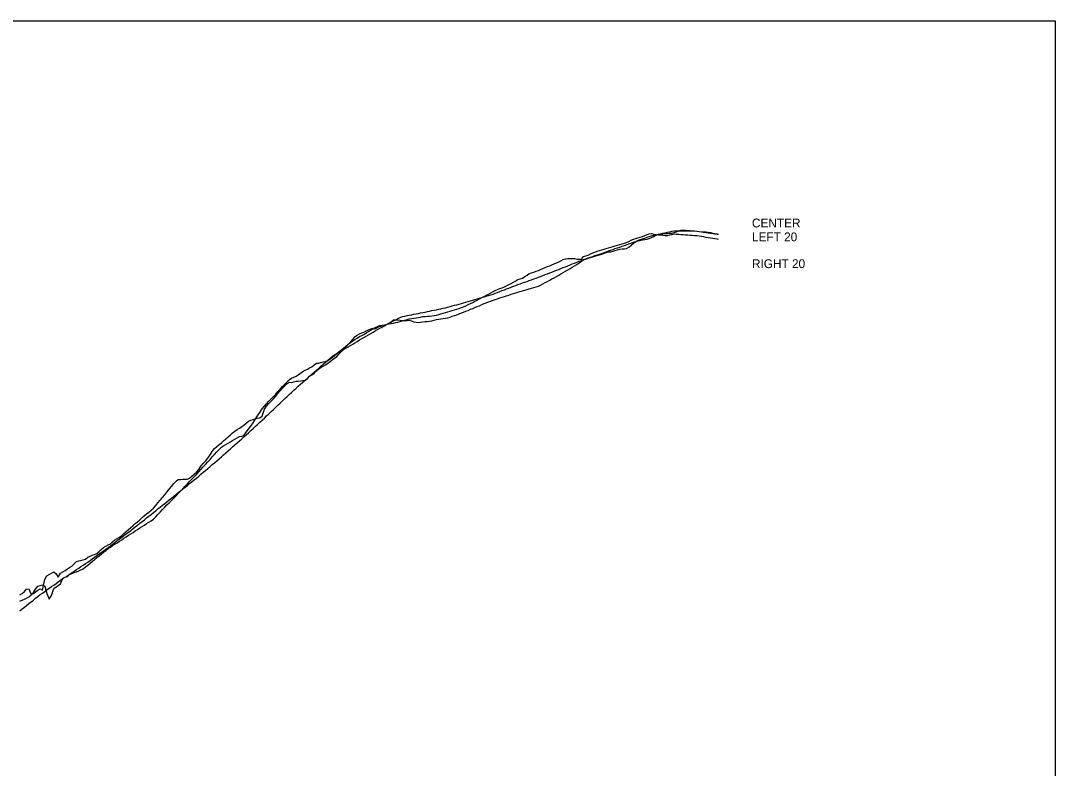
# Model space of a CAD drawing. Extents: x 1511486 to 1516886, y 901686 to 906985.
# Drawn here: x 1514602 to 1516886, y 905335 to 906985 of the extents above; entities that cross this region are included whole.
import ezdxf

# ---------------------------------------------------------------- set-up
doc = ezdxf.new("R2010")
doc.units = 0
for name, color, linetype in [('RD_DDB_Profile_EX', 7, 'Continuous'), ('RD_Sketch2', 7, 'Continuous'), ('RD_Sketch3', 7, 'Continuous')]:
    doc.layers.add(name, color=color, linetype=linetype)

msp = doc.modelspace()

# ---------------------------------------------------------------- linework, layer by layer
at = {"layer": 'RD_DDB_Profile_EX'}
for points in [[(1515574.7, 906361.2), (1515579.7, 906362.6), (1515584.7, 906364), (1515589.7, 906365.3), (1515594.7, 906366.8), (1515599.7, 906368.3), (1515604.7, 906369.8), (1515609.7, 906371.3), (1515614.7, 906372.8), (1515619.7, 906374.3), (1515624.7, 906375.7), (1515629.7, 906377.2), (1515634.7, 906378.7), (1515639.7, 906380.2), (1515644.7, 906381.9), (1515649.7, 906383.8), (1515654.7, 906385.7), (1515659.7, 906387.6), (1515664.7, 906389.5), (1515669.7, 906391.4), (1515674.7, 906393.4), (1515679.7, 906395.3), (1515684.7, 906397.2), (1515689.7, 906399.1), (1515694.7, 906401), (1515699.7, 906402.8), (1515704.7, 906404.6), (1515709.7, 906406.4), (1515714.7, 906408.2), (1515719.7, 906410), (1515724.7, 906411.8), (1515729.7, 906413.6), (1515734.7, 906415.4), (1515739.7, 906417.2), (1515744.7, 906419), (1515749.7, 906421), (1515754.7, 906422.9), (1515759.7, 906424.8), (1515764.7, 906426.7), (1515769.7, 906428.7), (1515774.7, 906430.6), (1515779.7, 906432.5), (1515784.7, 906434.4), (1515789.7, 906436.3), (1515794.7, 906438.3), (1515799.7, 906440.3), (1515804.7, 906442.3), (1515809.7, 906444.3), (1515814.7, 906446.3), (1515819.7, 906448.3), (1515824.7, 906450.3), (1515829.7, 906452.3), (1515834.7, 906454.3), (1515839.7, 906456.3), (1515844.7, 906458.2), (1515849.7, 906459.9), (1515854.7, 906461.6), (1515859.7, 906463.3), (1515864.7, 906465), (1515869.7, 906466.7), (1515874.7, 906468.4), (1515879.7, 906470.1), (1515884.7, 906471.8), (1515889.7, 906473.5), (1515894.7, 906475.2), (1515899.7, 906477), (1515904.7, 906478.7), (1515909.7, 906480.5), (1515914.7, 906482.2), (1515919.7, 906483.9), (1515924.7, 906485.7), (1515929.7, 906487.4), (1515934.7, 906489.1), (1515939.7, 906490.9), (1515944.7, 906492.8), (1515949.7, 906494.6), (1515954.7, 906496.4), (1515959.7, 906498.2), (1515964.7, 906500.2), (1515969.7, 906502), (1515974.7, 906503.8), (1515979.7, 906505.6), (1515984.7, 906507.4), (1515989.7, 906509.2), (1515994.7, 906510.5), (1515999.7, 906511.7), (1516004.7, 906512.8), (1516009.7, 906513.9), (1516014.7, 906515.1), (1516019.7, 906516.2), (1516024.7, 906517.3), (1516029.7, 906518.5), (1516034.7, 906519.6), (1516039.7, 906520.8), (1516044.7, 906521.3), (1516049.7, 906521.4), (1516054.7, 906521.4), (1516059.7, 906521.5), (1516064.7, 906521.6), (1516069.7, 906521.7), (1516074.7, 906521.7)], [(1516074.7, 906521.7), (1516079.7, 906521.6), (1516084.7, 906521.6), (1516089.7, 906521.5), (1516094.7, 906521), (1516099.7, 906520.2), (1516104.7, 906519.5), (1516109.7, 906518.7), (1516114.7, 906517.9), (1516119.7, 906517.1), (1516124.7, 906516.3), (1516129.7, 906515.5), (1516134.7, 906514.7), (1516139.7, 906513.9), (1516141.8, 906513.6)], [(1515074.7, 906049), (1515079.7, 906053.5), (1515084.7, 906057.9), (1515089.7, 906062.4), (1515094.7, 906066.8), (1515099.7, 906071.4), (1515104.7, 906076), (1515109.7, 906080.6), (1515114.7, 906085.2), (1515119.7, 906089.8), (1515124.7, 906094.4), (1515129.7, 906099.1), (1515134.7, 906103.7), (1515139.7, 906108.3), (1515144.7, 906112.9), (1515149.7, 906117.7), (1515154.7, 906122.4), (1515159.7, 906127.2), (1515164.7, 906132), (1515169.7, 906136.8), (1515174.7, 906141.5), (1515179.7, 906146.3), (1515184.7, 906151.1), (1515189.7, 906155.9), (1515194.7, 906160.5), (1515199.7, 906165), (1515204.7, 906169.5), (1515209.7, 906174), (1515214.7, 906178.5), (1515219.7, 906183), (1515224.7, 906187.5), (1515229.7, 906192), (1515234.7, 906196.5), (1515239.7, 906201), (1515244.7, 906205.4), (1515249.7, 906209.8), (1515254.7, 906214.2), (1515259.7, 906218.6), (1515264.7, 906222.9), (1515269.7, 906227.3), (1515274.7, 906231.6), (1515279.7, 906235.8), (1515284.7, 906240.1), (1515289.7, 906244.3), (1515294.7, 906248.1), (1515299.7, 906251.1), (1515304.7, 906253.9), (1515309.7, 906256.9), (1515314.7, 906259.9), (1515319.7, 906262.8), (1515324.7, 906265.7), (1515329.7, 906268.6), (1515334.7, 906271.5), (1515339.7, 906274.5), (1515344.7, 906277.6), (1515349.7, 906280.6), (1515354.7, 906283.5), (1515359.7, 906286.4), (1515364.7, 906289.3), (1515369.7, 906292.1), (1515374.7, 906295.1), (1515379.7, 906298.1), (1515384.7, 906300.9), (1515389.7, 906303.7), (1515394.7, 906306.5), (1515399.7, 906309.2), (1515404.7, 906312), (1515409.7, 906314.7), (1515414.7, 906317.1), (1515419.7, 906319.8), (1515424.7, 906322.5), (1515429.7, 906325.2), (1515434.7, 906327.9), (1515439.7, 906330.5), (1515444.7, 906332.3), (1515449.7, 906333.3), (1515454.7, 906334.3), (1515459.7, 906335.3), (1515464.7, 906336.3), (1515469.7, 906337.3), (1515474.7, 906338.3), (1515479.7, 906339.3), (1515484.7, 906340.3), (1515489.7, 906341.3), (1515494.7, 906342.2), (1515499.7, 906343.3), (1515504.7, 906344.5), (1515509.7, 906345.5), (1515514.7, 906346.2), (1515519.7, 906347.3), (1515524.7, 906348.5), (1515529.7, 906349.6), (1515534.7, 906350.7), (1515539.7, 906351.9), (1515544.7, 906353.1), (1515549.7, 906354.4), (1515554.7, 906355.8), (1515559.7, 906357.1), (1515564.7, 906358.4), (1515569.7, 906359.8), (1515574.7, 906361.2)], [(1514599.7, 905682.9), (1514604.7, 905686.9), (1514609.7, 905690.8), (1514614.7, 905694.8), (1514619.7, 905698.7), (1514624.7, 905702.7), (1514629.7, 905706.6), (1514634.7, 905710.5), (1514639.7, 905714.5), (1514644.7, 905718.5), (1514649.7, 905722), (1514654.7, 905725.5), (1514659.7, 905729.1), (1514664.7, 905732.6), (1514669.7, 905736.2), (1514674.7, 905739.7), (1514679.7, 905743.2), (1514684.7, 905746.8), (1514689.7, 905750.3), (1514694.7, 905753.8), (1514699.7, 905757.1), (1514704.7, 905760.4), (1514709.7, 905763.8), (1514714.7, 905767), (1514719.7, 905770.4), (1514724.7, 905773.7), (1514729.7, 905777), (1514734.7, 905780.3), (1514739.7, 905783.6), (1514744.7, 905786.9), (1514749.7, 905790.5), (1514754.7, 905794), (1514759.7, 905797.6), (1514764.7, 905801.1), (1514769.7, 905804.7), (1514774.7, 905808.3), (1514779.7, 905811.8), (1514784.7, 905815.4), (1514789.7, 905819), (1514794.7, 905822.6), (1514799.7, 905826.3), (1514804.7, 905830.1), (1514809.7, 905833.9), (1514814.7, 905837.7), (1514819.7, 905841.4), (1514824.7, 905845.2), (1514829.7, 905849), (1514834.7, 905852.8), (1514839.7, 905856.5), (1514844.7, 905860.3), (1514849.7, 905864.2), (1514854.7, 905868.2), (1514859.7, 905872.1), (1514864.7, 905876), (1514869.7, 905880), (1514874.7, 905883.9), (1514879.7, 905887.8), (1514884.7, 905891.7), (1514889.7, 905895.6), (1514894.7, 905899.5), (1514899.7, 905903.5), (1514904.7, 905907.6), (1514909.7, 905911.6), (1514914.7, 905915.7), (1514919.7, 905919.6), (1514924.7, 905923.6), (1514929.7, 905927.6), (1514934.7, 905931.6), (1514939.7, 905935.6), (1514944.7, 905939.6), (1514949.7, 905943.6), (1514954.7, 905947.6), (1514959.7, 905951.7), (1514964.7, 905955.7), (1514969.7, 905959.7), (1514974.7, 905963.7), (1514979.7, 905967.8), (1514984.7, 905971.8), (1514989.7, 905975.9), (1514994.7, 905980), (1514999.7, 905984.2), (1515004.7, 905988.5), (1515009.7, 905992.7), (1515014.7, 905996.9), (1515019.7, 906001.2), (1515024.7, 906005.4), (1515029.7, 906009.6), (1515034.7, 906013.9), (1515039.7, 906018.2), (1515044.7, 906022.6), (1515049.7, 906027), (1515054.7, 906031.4), (1515059.7, 906035.8), (1515064.7, 906040.2), (1515069.7, 906044.6), (1515074.7, 906049)]]:
    msp.add_lwpolyline(points, dxfattribs=at)
at = {"layer": 'RD_Sketch2'}
for points in [[(1515574.7, 906340.2), (1515579.7, 906342.1), (1515584.7, 906344), (1515589.7, 906345.9), (1515594.7, 906348.4), (1515599.7, 906350.3), (1515604.7, 906352.3), (1515609.7, 906354.2), (1515614.7, 906356.1), (1515619.7, 906358.7), (1515624.7, 906360.8), (1515629.7, 906362.7), (1515634.7, 906364.5), (1515639.7, 906366.4), (1515644.7, 906368.3), (1515649.7, 906369.7), (1515654.7, 906371.5), (1515659.7, 906373.4), (1515664.7, 906374.8), (1515669.7, 906376.4), (1515674.7, 906378.1), (1515679.7, 906379.7), (1515684.7, 906381.4), (1515689.7, 906383.2), (1515694.7, 906384.8), (1515699.7, 906386.3), (1515704.7, 906387.7), (1515709.7, 906389.3), (1515714.7, 906390.7), (1515719.7, 906392.1), (1515724.7, 906393.4), (1515729.7, 906394.8), (1515734.7, 906396.2), (1515739.7, 906397.6), (1515744.7, 906399.6), (1515749.7, 906401.8), (1515754.7, 906404.7), (1515759.7, 906407.3), (1515764.7, 906410), (1515769.7, 906412.7), (1515774.7, 906415.4), (1515779.7, 906418.1), (1515784.7, 906420.8), (1515789.7, 906423.6), (1515794.7, 906426.4), (1515799.7, 906429.4), (1515804.7, 906432.3), (1515809.7, 906435.3), (1515814.7, 906438.2), (1515819.7, 906441.2), (1515824.7, 906444), (1515829.7, 906447.1), (1515834.7, 906450.7), (1515839.7, 906454.7), (1515844.7, 906457.5), (1515849.7, 906459.2), (1515854.7, 906460.9), (1515859.7, 906462.5), (1515864.7, 906463.9), (1515869.7, 906465.4), (1515874.7, 906466.9), (1515879.7, 906468.5), (1515884.7, 906470.2), (1515889.7, 906471.9), (1515894.7, 906473.7), (1515899.7, 906475), (1515904.7, 906475.5), (1515909.7, 906476.8), (1515914.7, 906478.1), (1515919.7, 906479.5), (1515924.7, 906480.9), (1515929.7, 906481.7), (1515934.7, 906482), (1515939.7, 906482.3), (1515944.7, 906485.5), (1515949.7, 906489.8), (1515954.7, 906494.2), (1515959.7, 906498.2), (1515964.7, 906499.3), (1515969.7, 906500.3), (1515974.7, 906501.3), (1515979.7, 906502.4), (1515984.7, 906503.4), (1515989.7, 906504.5), (1515994.7, 906506.6), (1515999.7, 906509.2), (1516004.7, 906511.7), (1516009.7, 906514.3), (1516014.7, 906514.8), (1516019.7, 906515.1), (1516024.7, 906515.4), (1516029.7, 906515.7), (1516034.7, 906516.1), (1516039.7, 906516.4), (1516044.7, 906517.6), (1516049.7, 906519.5), (1516054.7, 906521.4), (1516059.7, 906523.3), (1516064.7, 906523), (1516069.7, 906522.7), (1516074.7, 906522.4)], [(1516074.7, 906522.4), (1516079.7, 906522.1), (1516084.7, 906521.8), (1516089.7, 906521.5), (1516094.7, 906520.5), (1516099.7, 906519.8), (1516104.7, 906519.5), (1516109.7, 906519.3), (1516114.7, 906519), (1516119.7, 906518.6), (1516124.7, 906517.6), (1516129.7, 906516.7), (1516134.7, 906515.8), (1516139.7, 906514.8), (1516141.8, 906514.4)], [(1515574.7, 906352.1), (1515579.7, 906354), (1515584.7, 906356.3), (1515589.7, 906358.6), (1515594.7, 906360.8), (1515599.7, 906363.5), (1515604.7, 906366.1), (1515609.7, 906368.8), (1515614.7, 906371.4), (1515619.7, 906374), (1515624.7, 906376.7), (1515629.7, 906379.3), (1515634.7, 906382), (1515639.7, 906384.6), (1515644.7, 906387.3), (1515649.7, 906390), (1515654.7, 906392.1), (1515659.7, 906394), (1515664.7, 906395.9), (1515669.7, 906397.8), (1515674.7, 906400.1), (1515679.7, 906402.7), (1515684.7, 906405.3), (1515689.7, 906407.9), (1515694.7, 906410.8), (1515699.7, 906413.8), (1515704.7, 906415.4), (1515709.7, 906417.3), (1515714.7, 906420.6), (1515719.7, 906423.9), (1515724.7, 906427.2), (1515729.7, 906429), (1515734.7, 906430.5), (1515739.7, 906432.1), (1515744.7, 906433.9), (1515749.7, 906436), (1515754.7, 906438.1), (1515759.7, 906440.3), (1515764.7, 906442.4), (1515769.7, 906444.4), (1515774.7, 906446.5), (1515779.7, 906448.5), (1515784.7, 906450.6), (1515789.7, 906452.7), (1515794.7, 906455.2), (1515799.7, 906458.2), (1515804.7, 906459.9), (1515809.7, 906460.4), (1515814.7, 906460.3), (1515819.7, 906460.2), (1515824.7, 906460.1), (1515829.7, 906459), (1515834.7, 906458.9), (1515839.7, 906458.9), (1515844.7, 906465.2), (1515849.7, 906466), (1515854.7, 906468), (1515859.7, 906470.7), (1515864.7, 906472.7), (1515869.7, 906474.5), (1515874.7, 906476.3), (1515879.7, 906478), (1515884.7, 906479.7), (1515889.7, 906480.9), (1515894.7, 906482.4), (1515899.7, 906483.8), (1515904.7, 906485.3), (1515909.7, 906486.9), (1515914.7, 906488.4), (1515919.7, 906489.9), (1515924.7, 906491.4), (1515929.7, 906492.9), (1515934.7, 906494.4), (1515939.7, 906496), (1515944.7, 906498.3), (1515949.7, 906500.6), (1515954.7, 906502.8), (1515959.7, 906504.6), (1515964.7, 906506.4), (1515969.7, 906507.6), (1515974.7, 906508.8), (1515979.7, 906511.5), (1515984.7, 906513.7), (1515989.7, 906515.2), (1515994.7, 906515.7), (1515999.7, 906514.3), (1516004.7, 906513.3), (1516009.7, 906512.8), (1516014.7, 906512.3), (1516019.7, 906511.8), (1516024.7, 906511.4), (1516029.7, 906511.4), (1516034.7, 906512.5), (1516039.7, 906513.6), (1516044.7, 906514.6), (1516049.7, 906514.4), (1516054.7, 906514.1), (1516059.7, 906513.7), (1516064.7, 906513.2), (1516069.7, 906512.8), (1516074.7, 906512.5)], [(1516074.7, 906512.5), (1516079.7, 906512.2), (1516084.7, 906511.8), (1516089.7, 906511.5), (1516094.7, 906511), (1516099.7, 906510.4), (1516104.7, 906509.6), (1516109.7, 906508.7), (1516114.7, 906507.8), (1516119.7, 906506.9), (1516124.7, 906506.1), (1516129.7, 906505.2), (1516134.7, 906504.4), (1516139.7, 906503.7), (1516141.8, 906503.4)], [(1515074.7, 906079.7), (1515079.7, 906083.1), (1515084.7, 906086.3), (1515089.7, 906089.4), (1515094.7, 906092.7), (1515099.7, 906097.2), (1515104.7, 906101.1), (1515109.7, 906103.3), (1515114.7, 906104.9), (1515119.7, 906106.3), (1515124.7, 906107.7), (1515129.7, 906108.8), (1515134.7, 906112.1), (1515139.7, 906128.1), (1515144.7, 906134.2), (1515149.7, 906140.1), (1515154.7, 906145.6), (1515159.7, 906151), (1515164.7, 906156.7), (1515169.7, 906162.5), (1515174.7, 906168.3), (1515179.7, 906174.1), (1515184.7, 906179.7), (1515189.7, 906184.5), (1515194.7, 906187.7), (1515199.7, 906187), (1515204.7, 906188.2), (1515209.7, 906189.4), (1515214.7, 906190), (1515219.7, 906190.6), (1515224.7, 906191.2), (1515229.7, 906191.8), (1515234.7, 906195.8), (1515239.7, 906200.5), (1515244.7, 906203.9), (1515249.7, 906207.2), (1515254.7, 906212.2), (1515259.7, 906216.9), (1515264.7, 906219.7), (1515269.7, 906222.5), (1515274.7, 906225.7), (1515279.7, 906229.3), (1515284.7, 906233.1), (1515289.7, 906237.1), (1515294.7, 906240.8), (1515299.7, 906244.4), (1515304.7, 906250.1), (1515309.7, 906255.3), (1515314.7, 906260.2), (1515319.7, 906265.3), (1515324.7, 906270.6), (1515329.7, 906276), (1515334.7, 906281.6), (1515339.7, 906287.5), (1515344.7, 906291), (1515349.7, 906294.2), (1515354.7, 906296.2), (1515359.7, 906298.2), (1515364.7, 906300.5), (1515369.7, 906302.9), (1515374.7, 906305.2), (1515379.7, 906307), (1515384.7, 906305.3), (1515389.7, 906308.3), (1515394.7, 906311.1), (1515399.7, 906309.7), (1515404.7, 906312), (1515409.7, 906314.9), (1515414.7, 906316.1), (1515419.7, 906317.2), (1515424.7, 906318), (1515429.7, 906319), (1515434.7, 906320.2), (1515439.7, 906321.6), (1515444.7, 906322.6), (1515449.7, 906324.2), (1515454.7, 906326), (1515459.7, 906327.3), (1515464.7, 906328), (1515469.7, 906328.9), (1515474.7, 906329.8), (1515479.7, 906330.3), (1515484.7, 906331.1), (1515489.7, 906332.1), (1515494.7, 906332.5), (1515499.7, 906332.8), (1515504.7, 906333.1), (1515509.7, 906333.7), (1515514.7, 906334.6), (1515519.7, 906335.7), (1515524.7, 906336.8), (1515529.7, 906338.1), (1515534.7, 906339.6), (1515539.7, 906341.3), (1515544.7, 906342.9), (1515549.7, 906344.2), (1515554.7, 906345.4), (1515559.7, 906346.8), (1515564.7, 906348.4), (1515569.7, 906350.2), (1515574.7, 906352.1)], [(1515074.7, 906061.5), (1515079.7, 906064.4), (1515084.7, 906067.3), (1515089.7, 906068.6), (1515094.7, 906069.9), (1515099.7, 906077.3), (1515104.7, 906083.4), (1515109.7, 906090.2), (1515114.7, 906097.7), (1515119.7, 906105.3), (1515124.7, 906112.9), (1515129.7, 906120.7), (1515134.7, 906128.5), (1515139.7, 906134.8), (1515144.7, 906139.9), (1515149.7, 906145.4), (1515154.7, 906150.9), (1515159.7, 906156.1), (1515164.7, 906161.3), (1515169.7, 906166.7), (1515174.7, 906172.1), (1515179.7, 906177.6), (1515184.7, 906183.1), (1515189.7, 906188.5), (1515194.7, 906192.7), (1515199.7, 906196), (1515204.7, 906198.3), (1515209.7, 906200.5), (1515214.7, 906203.4), (1515219.7, 906207.1), (1515224.7, 906210.7), (1515229.7, 906214), (1515234.7, 906216.4), (1515239.7, 906218.8), (1515244.7, 906221.3), (1515249.7, 906226), (1515254.7, 906229.2), (1515259.7, 906229.2), (1515264.7, 906230.8), (1515269.7, 906232.2), (1515274.7, 906233.3), (1515279.7, 906235.3), (1515284.7, 906238.7), (1515289.7, 906242.1), (1515294.7, 906246.7), (1515299.7, 906250.9), (1515304.7, 906254.9), (1515309.7, 906258.8), (1515314.7, 906262.8), (1515319.7, 906267), (1515324.7, 906271), (1515329.7, 906274.9), (1515334.7, 906278.7), (1515339.7, 906281.7), (1515344.7, 906284.4), (1515349.7, 906288.2), (1515354.7, 906290.5), (1515359.7, 906292.7), (1515364.7, 906296), (1515369.7, 906299.3), (1515374.7, 906302.5), (1515379.7, 906305.5), (1515384.7, 906308.1), (1515389.7, 906310.5), (1515394.7, 906312.2), (1515399.7, 906313.2), (1515404.7, 906314.1), (1515409.7, 906315), (1515414.7, 906317.7), (1515419.7, 906320.3), (1515424.7, 906325), (1515429.7, 906325.2), (1515434.7, 906324.9), (1515439.7, 906324.6), (1515444.7, 906323.5), (1515449.7, 906323.2), (1515454.7, 906323.8), (1515459.7, 906324.3), (1515464.7, 906323), (1515469.7, 906321), (1515474.7, 906319.6), (1515479.7, 906319.2), (1515484.7, 906319.9), (1515489.7, 906320.7), (1515494.7, 906321.4), (1515499.7, 906321.6), (1515504.7, 906321.9), (1515509.7, 906322.7), (1515514.7, 906324.3), (1515519.7, 906325.9), (1515524.7, 906326.5), (1515529.7, 906327.1), (1515534.7, 906327.7), (1515539.7, 906328.4), (1515544.7, 906329.2), (1515549.7, 906331), (1515554.7, 906332.8), (1515559.7, 906334.7), (1515564.7, 906336.4), (1515569.7, 906338.4), (1515574.7, 906340.2)], [(1514599.7, 905717.8), (1514604.7, 905720.8), (1514609.7, 905725.7), (1514614.7, 905730.7), (1514619.7, 905731.1), (1514624.7, 905718.6), (1514629.7, 905720.9), (1514634.7, 905724.6), (1514639.7, 905728.2), (1514644.7, 905731), (1514649.7, 905728.2), (1514654.7, 905751.8), (1514659.7, 905760), (1514664.7, 905762.9), (1514669.7, 905765.8), (1514674.7, 905768.7), (1514679.7, 905764.8), (1514684.7, 905757.3), (1514689.7, 905765.8), (1514694.7, 905769), (1514699.7, 905772.1), (1514704.7, 905775.3), (1514709.7, 905778.1), (1514714.7, 905781.7), (1514719.7, 905786.7), (1514724.7, 905791.8), (1514729.7, 905793.1), (1514734.7, 905794.2), (1514739.7, 905795.3), (1514744.7, 905796.8), (1514749.7, 905801.5), (1514754.7, 905803.5), (1514759.7, 905805.5), (1514764.7, 905807.4), (1514769.7, 905809.3), (1514774.7, 905813.8), (1514779.7, 905818.2), (1514784.7, 905822.6), (1514789.7, 905825.7), (1514794.7, 905828.3), (1514799.7, 905830.9), (1514804.7, 905834.8), (1514809.7, 905839.4), (1514814.7, 905842.4), (1514819.7, 905845.2), (1514824.7, 905848.9), (1514829.7, 905853.3), (1514834.7, 905857.7), (1514839.7, 905862.1), (1514844.7, 905866.6), (1514849.7, 905871.3), (1514854.7, 905875.2), (1514859.7, 905879.1), (1514864.7, 905883.8), (1514869.7, 905888.6), (1514874.7, 905893.2), (1514879.7, 905897), (1514884.7, 905900.8), (1514889.7, 905904.7), (1514894.7, 905909.4), (1514899.7, 905915.5), (1514904.7, 905921.5), (1514909.7, 905927.2), (1514914.7, 905933), (1514919.7, 905938.9), (1514924.7, 905945), (1514929.7, 905951.2), (1514934.7, 905957.4), (1514939.7, 905963.5), (1514944.7, 905969.3), (1514949.7, 905972.4), (1514954.7, 905972.9), (1514959.7, 905973.2), (1514964.7, 905973.4), (1514969.7, 905973.5), (1514974.7, 905975.5), (1514979.7, 905979.9), (1514984.7, 905984.3), (1514989.7, 905988.5), (1514994.7, 905994.7), (1514999.7, 906002.3), (1515004.7, 906008), (1515009.7, 906012.8), (1515014.7, 906019.9), (1515019.7, 906027.4), (1515024.7, 906034.8), (1515029.7, 906041.4), (1515034.7, 906045.5), (1515039.7, 906049.6), (1515044.7, 906053.7), (1515049.7, 906058.1), (1515054.7, 906062.3), (1515059.7, 906066.8), (1515064.7, 906071.3), (1515069.7, 906075.6), (1515074.7, 906079.7)], [(1514599.7, 905703.9), (1514604.7, 905706.1), (1514609.7, 905708.3), (1514614.7, 905710.5), (1514619.7, 905713.6), (1514624.7, 905718.4), (1514629.7, 905723.3), (1514634.7, 905730.3), (1514639.7, 905737.3), (1514644.7, 905739), (1514649.7, 905740.5), (1514654.7, 905737.1), (1514659.7, 905721.2), (1514664.7, 905708.5), (1514669.7, 905716.9), (1514674.7, 905732), (1514679.7, 905735.4), (1514684.7, 905738.7), (1514689.7, 905742.3), (1514694.7, 905754.8), (1514699.7, 905756.8), (1514704.7, 905758.8), (1514709.7, 905762.7), (1514714.7, 905765), (1514719.7, 905767.1), (1514724.7, 905769.2), (1514729.7, 905771.3), (1514734.7, 905773.4), (1514739.7, 905775.5), (1514744.7, 905779.7), (1514749.7, 905783.8), (1514754.7, 905787.8), (1514759.7, 905791.8), (1514764.7, 905796.2), (1514769.7, 905800.2), (1514774.7, 905804.2), (1514779.7, 905808.1), (1514784.7, 905812.1), (1514789.7, 905816.1), (1514794.7, 905820.1), (1514799.7, 905823.5), (1514804.7, 905826.8), (1514809.7, 905829.6), (1514814.7, 905832.9), (1514819.7, 905836.3), (1514824.7, 905839.6), (1514829.7, 905843), (1514834.7, 905846.3), (1514839.7, 905849.6), (1514844.7, 905852.9), (1514849.7, 905856), (1514854.7, 905859.2), (1514859.7, 905862.4), (1514864.7, 905865.8), (1514869.7, 905869), (1514874.7, 905872.2), (1514879.7, 905875.4), (1514884.7, 905878.6), (1514889.7, 905881.7), (1514894.7, 905885.4), (1514899.7, 905890.6), (1514904.7, 905895.7), (1514909.7, 905900.9), (1514914.7, 905906.1), (1514919.7, 905911.3), (1514924.7, 905916.5), (1514929.7, 905921.1), (1514934.7, 905926.4), (1514939.7, 905931.6), (1514944.7, 905936.8), (1514949.7, 905942), (1514954.7, 905947.2), (1514959.7, 905952.3), (1514964.7, 905957.6), (1514969.7, 905962.8), (1514974.7, 905968.1), (1514979.7, 905973.4), (1514984.7, 905978.7), (1514989.7, 905984), (1514994.7, 905989.4), (1514999.7, 905994.9), (1515004.7, 906000.4), (1515009.7, 906006), (1515014.7, 906011.4), (1515019.7, 906016.9), (1515024.7, 906022.5), (1515029.7, 906028.1), (1515034.7, 906033.6), (1515039.7, 906039.2), (1515044.7, 906044.3), (1515049.7, 906047.1), (1515054.7, 906050), (1515059.7, 906053), (1515064.7, 906055.8), (1515069.7, 906058.7), (1515074.7, 906061.5)]]:
    msp.add_lwpolyline(points, dxfattribs=at)
at = {"layer": 'RD_Sketch3'}
msp.add_lwpolyline([(1511486.2, 906985.3), (1516886.2, 906985.3), (1516886.2, 903685.3), (1511486.2, 903685.3)], close=True, dxfattribs=at)

# ---------------------------------------------------------------- texts
at = {"layer": 'RD_DDB_Profile_EX'}
msp.add_text('CENTER', height=19.5, dxfattribs=at).set_placement((1516216.4, 906529))
at = {"layer": 'RD_Sketch2'}
for s, p in [('LEFT 20', (1516216.4, 906498.4)), ('RIGHT 20', (1516216.4, 906439.2))]:
    msp.add_text(s, height=19.5, dxfattribs=at).set_placement(p)

doc.saveas('drawing.dxf')
